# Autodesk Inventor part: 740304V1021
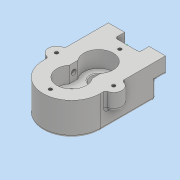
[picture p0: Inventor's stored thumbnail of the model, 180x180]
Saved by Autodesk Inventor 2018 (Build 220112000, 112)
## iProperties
Created: 2024-03
Part Number: 740304V1021
Material: 일반
Document SubType Name: Modeling
Designer: home
Density: 1 g/cm^3
Appearance: 기본값
Author: home
## Parameters: d7 = 103 mm, d8 = 0, d9 = 35 mm, d10 = 60 deg, d13 = 35 mm, d14 = 14 mm, d20 = 90 deg, d21 = 33 mm, d22 = 15 mm, d24 = 103 mm, d25 = 0, d27 = 0, d28 = 36 mm, d29 = 36 mm, d30 = 14 mm, d31 = 14 mm, d33 = 0, d41 = 15 mm, d42 = 15 mm, d43 = 12 mm, d44 = 0, d45 = 32 mm, d46 = 52 mm, d47 = 6 mm, d48 = 0, d50 = 0, d52 = 30 deg, d53 = 25 mm, d54 = 7.3 mm, d55 = 0.7 mm, d56 = 90 deg, d57 = 63.5 mm, d58 = 63.5 mm, d63 = 0, d64 = 26 mm, d65 = 26 mm, d66 = 4.134 mm, d68 = 4 mm, d69 = 2 mm, d70 = 90 deg, d71 = 12 mm, d72 = 118 deg, d77 = 42 mm, d80 = 360 deg, d82 = 3.242 mm, d83 = 8 mm, d84 = 3.023 mm, d85 = 2 mm, d86 = 82 deg, d88 = 118 deg, d90 = 0, d91 = 0.5 mm, d92 = 0, d94 = 10 mm, d97 = 6 mm, d98 = 6 mm, d104 = 63.5 mm, d105 = 8 mm, d106 = 55.5 mm, d107 = 0, d108 = 0, d111 = 16 mm, d112 = 0, d113 = 16 mm, d114 = 0, d115 = 3 mm, d116 = 3 mm, d117 = 3 mm, d118 = 3 mm, d119 = 3 mm, d120 = 3 mm, d121 = 3 mm, d122 = 1 mm, d123 = 2 mm, d124 = 45 deg, d125 = 1 mm, d126 = 2 mm, d127 = 45 deg
